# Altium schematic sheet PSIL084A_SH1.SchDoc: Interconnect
size 431 x 279 mm; Date: Not shown in title block; ApprovedBy: Not shown in title block; CheckedBy: Not shown in title block; Author: Not shown in title block; CompanyName: Not shown in title block; DrawnBy: D Strasser; Engineer: Not shown in title block; Organization: Not shown in title block; Address1: Not shown in title block; Address2: Not shown in title block; Address3: Not shown in title block; Address4: Not shown in title block; DocumentNumber: 1; Revision: Use project parameter SCH_Rev; SheetNumber: 1; SheetTotal: 3; PageSetup: Record=PageOptions¦CenterHorizontal=True¦CenterVertical=True¦PrintScale=1.00¦XCorrection=1.00¦YCorrection=1.00¦PrintKind=0¦BorderSize=5000000¦LeftOffset=0¦BottomOffset=0¦Orientation=2¦PaperLength=1000¦PaperWidth=1000¦Scale=100¦PaperSource=15¦PrintQuality=600¦MediaType=1¦DitherType=10¦PaperKind=Letter¦PrintScaleMode=1
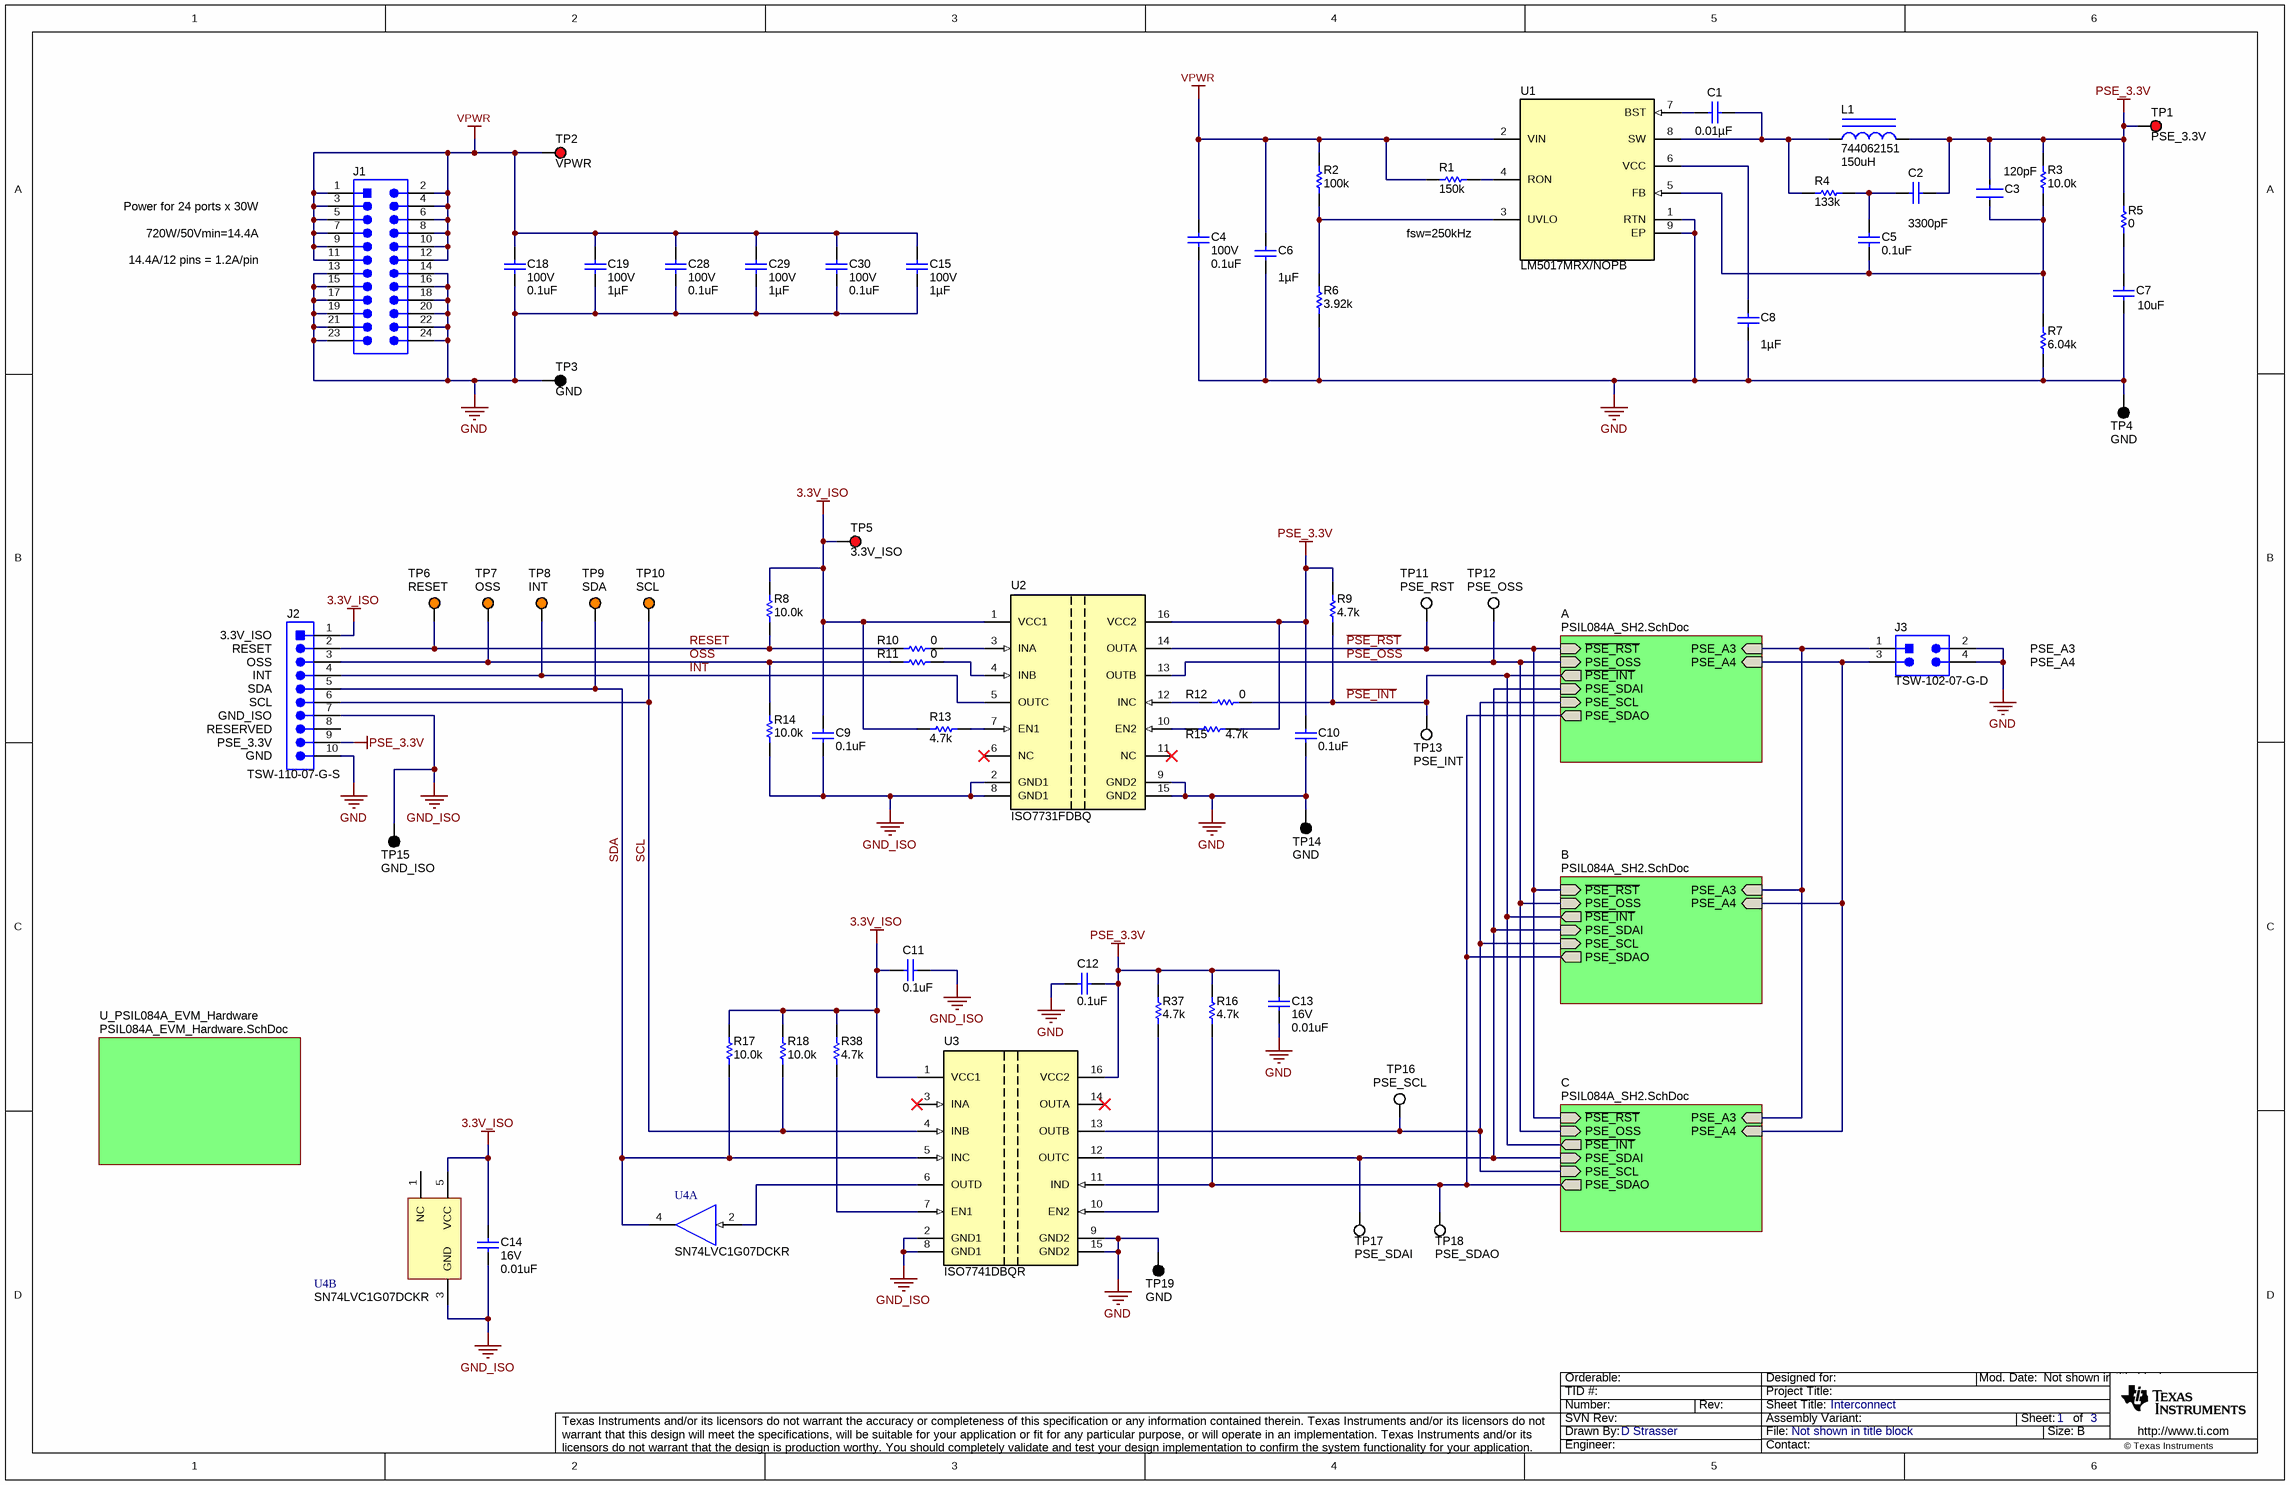
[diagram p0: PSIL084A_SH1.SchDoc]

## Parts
C1  ValueDisplayed: 0.01µF  [0603]  (hidden comment: 885012206089)
C2  ValueDisplayed: 3300pF  [0603]  (hidden comment: GRM1885C1H332JA01D)
C3  Cap_F: 120pF  [FP-GCM1555C1H121FA16D_0402-MFG]  (hidden comment: GCM1555C1H121FA16D)
C4  VDC_V: 100V  ValueDisplayed: 0.1uF  [0805_HV]  (hidden comment: C2012X7R2A104K125AA)
C5  ValueDisplayed: 0.1uF  [0603]  (hidden comment: 885012206095)
C6  ValueDisplayed: 1µF  [1206]  (hidden comment: GCJ31CR72A105KA01K)
C7  ValueDisplayed: 10uF  [0805_HV]  (hidden comment: 885012207026)
C8  ValueDisplayed: 1µF  [0603]  (hidden comment: CL10B105MO8NNWC)
C9  ValueDisplayed: 0.1uF  [0603]  (hidden comment: 885012206095)
C10  ValueDisplayed: 0.1uF  [0603]  (hidden comment: 885012206095)
C11  ValueDisplayed: 0.1uF  [0603]  (hidden comment: 885012206095)
C12  ValueDisplayed: 0.1uF  [0603]  (hidden comment: 885012206095)
C13  VDC_V: 16V  ValueDisplayed: 0.01uF  [0402]  (hidden comment: 885012205031)
C14  VDC_V: 16V  ValueDisplayed: 0.01uF  [0402]  (hidden comment: 885012205031)
C15  VDC_V: 100V  ValueDisplayed: 1µF  [1206]  (hidden comment: GCJ31CR72A105KA01K)
C18  VDC_V: 100V  ValueDisplayed: 0.1uF  [0805L]  (hidden comment: C2012X7R2A104K125AA)
C19  VDC_V: 100V  ValueDisplayed: 1µF  [1206]  (hidden comment: GCJ31CR72A105KA01K)
C28  VDC_V: 100V  ValueDisplayed: 0.1uF  [0805L]  (hidden comment: C2012X7R2A104K125AA)
C29  VDC_V: 100V  ValueDisplayed: 1µF  [1206]  (hidden comment: GCJ31CR72A105KA01K)
C30  VDC_V: 100V  ValueDisplayed: 0.1uF  [0805L]  (hidden comment: C2012X7R2A104K125AA)
J1  TSW-112-07-G-D  [TSW-112-07-G-D]  (value not drawn)
J2  TSW-110-07-G-S  [TSW-110-07-G-S]
J3  TSW-102-07-G-D  [TSW-102-07-G-D]
L1  744062151  ValueDisplayed: 150uH  [WE-TPC_6823]
R1  ValueDisplayed: 150k  [0402]  (hidden comment: CRCW0402150KFKED)
R2  ValueDisplayed: 100k  [0402]  (hidden comment: CRCW0402100KFKED)
R3  ValueDisplayed: 10.0k  [0402]  (hidden comment: CRCW040210K0FKED)
R4  ValueDisplayed: 133k  [0402]  (hidden comment: CRCW0402133KFKED)
R5  ValueDisplayed: 0  [0603]  (hidden comment: RC0603JR-070RL)
R6  ValueDisplayed: 3.92k  [0402]  (hidden comment: CRCW04023K92FKED)
R7  ValueDisplayed: 6.04k  [0402]  (hidden comment: CRCW04026K04FKED)
R8  ValueDisplayed: 10.0k  [0402]  (hidden comment: CRCW040210K0FKED)
R9  ValueDisplayed: 4.7k  [0402]  (hidden comment: CRCW04024K70JNED)
R10  ValueDisplayed: 0  [0402]  (hidden comment: ERJ-2GE0R00X)
R11  ValueDisplayed: 0  [0402]  (hidden comment: ERJ-2GE0R00X)
R12  ValueDisplayed: 0  [0402]  (hidden comment: ERJ-2GE0R00X)
R13  ValueDisplayed: 4.7k  [0402]  (hidden comment: CRCW04024K70JNED)
R14  ValueDisplayed: 10.0k  [0402]  (hidden comment: CRCW040210K0FKED)
R15  ValueDisplayed: 4.7k  [0402]  (hidden comment: CRCW04024K70JNED)
R16  ValueDisplayed: 4.7k  [0402]  (hidden comment: CRCW04024K70JNED)
R17  ValueDisplayed: 10.0k  [0402]  (hidden comment: CRCW040210K0FKED)
R18  ValueDisplayed: 10.0k  [0402]  (hidden comment: CRCW040210K0FKED)
R37  ValueDisplayed: 4.7k  [0402]  (hidden comment: CRCW04024K70JNED)
R38  ValueDisplayed: 4.7k  [0402]  (hidden comment: CRCW04024K70JNED)
TP1  PSE_3.3V  [Keystone5000]
TP2  VPWR  [Keystone5000]
TP3  GND  [Keystone5001]
TP4  GND  [Keystone5001]
TP5  3.3V_ISO  [Keystone5000]
TP6  RESET  [Keystone5003]
TP7  OSS  [Keystone5003]
TP8  INT  [Keystone5003]
TP9  SDA  [Keystone5003]
TP10  SCL  [Keystone5003]
TP11  PSE_RST  [Keystone5002]
TP12  PSE_OSS  [Keystone5002]
TP13  PSE_INT  [Keystone5002]
TP14  GND  [Keystone5001]
TP15  GND_ISO  [Keystone5001]
TP16  PSE_SCL  [Keystone5002]
TP17  PSE_SDAI  [Keystone5002]
TP18  PSE_SDAO  [Keystone5002]
TP19  GND  [Keystone5001]
U1  LM5017MRX/NOPB  [DDA0008B_N]
U2  ISO7731FDBQ  [DBQ0016A_N]
U3  ISO7741DBQR  [DBQ0016A_N]
U4  SN74LVC1G07DCKR  [DCK0005A_N]  (parts A,B of 2)

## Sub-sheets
A = PSIL084A_SH2.SchDoc: ~{PSE_RST} (in), PSE_SCL (in), PSE_SDAI (in), PSE_OSS (in), ~{PSE_INT} (out), PSE_A4 (in), PSE_A3 (in), PSE_SDAO (out)
B = PSIL084A_SH2.SchDoc: ~{PSE_RST} (in), PSE_SCL (in), PSE_SDAI (in), PSE_OSS (in), ~{PSE_INT} (out), PSE_A4 (in), PSE_A3 (in), PSE_SDAO (out)
C = PSIL084A_SH2.SchDoc: ~{PSE_RST} (in), PSE_SCL (in), PSE_SDAI (in), PSE_OSS (in), ~{PSE_INT} (out), PSE_A4 (in), PSE_A3 (in), PSE_SDAO (out)
U_PSIL084A_EVM_Hardware = PSIL084A_EVM_Hardware.SchDoc: no entries

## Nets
3.3V_ISO: C9.1 C11.1 C14.2 J2.1 R8.1 R13.2 R17.1 R18.1 R38.2 TP5.1 U2.1(VCC1) U3.1(VCC1) U4.5(VCC)
GND: C4.1 C6.1 C7.2 C8.2 C10.2 C12.2 C13.1 C15.1 C18.1 C19.1 C28.1 C29.1 C30.1 J1.13 J1.14 J1.15 J1.16 J1.17 J1.18 J1.19 J1.20 J1.21 J1.22 J1.23 J1.24 J2.10 J3.2 J3.4 R6.2 R7.2 TP3.1 TP4.1 TP14.1 TP19.1 U1.1(RTN) U1.9(EP) U2.9(GND2) U2.15(GND2) U3.9(GND2) U3.15(GND2)
GND_ISO: C9.2 C11.2 C14.1 J2.7 R14.2 TP15.1 U2.2(GND1) U2.8(GND1) U3.2(GND1) U3.8(GND1) U4.3(GND)
PSE_3.3V: C2.1 C3.1 C10.1 C12.1 C13.2 J2.9 L1.2 R3.1 R5.1 R9.2 R15.1 R16.2 R37.2 TP1.1 U2.16(VCC2) U3.16(VCC2)
VPWR: C4.2 C6.2 C15.2 C18.2 C19.2 C28.2 C29.2 C30.2 J1.1 J1.2 J1.3 J1.4 J1.5 J1.6 J1.7 J1.8 J1.9 J1.10 J1.11 J1.12 R1.1 R2.1 TP2.1 U1.2(VIN)
~{PSE_INT}: R9.1 R12.2 TP13.1 ; sheet A/~{PSE_INT}, sheet B/~{PSE_INT}, sheet C/~{PSE_INT}
~{PSE_RST}: TP11.1 U2.14(OUTA) ; sheet A/~{PSE_RST}, sheet B/~{PSE_RST}, sheet C/~{PSE_RST}
INT: J2.4 TP8.1 U2.5(OUTC)
OSS: J2.3 R11.1 R14.1 TP7.1
PSE_OSS: TP12.1 U2.13(OUTB) ; sheet A/PSE_OSS, sheet B/PSE_OSS, sheet C/PSE_OSS
RESET: J2.2 R8.2 R10.1 TP6.1
SCL: J2.6 R18.2 TP10.1 U3.4(INB)
SDA: J2.5 R17.2 TP9.1 U3.5(INC) U4.4(Y)
NetC1_1: C1.1 L1.1 R4.1 U1.8(SW)
NetC1_2: C1.2 U1.7(BST)
NetC2_2: C2.2 C5.1 R4.2
NetC3_2: C3.2 C5.2 R3.2 R7.1 U1.5(FB)
NetC7_1: C7.1 R5.2
NetC8_1: C8.1 U1.6(VCC)
NetJ3_1: J3.1 ; sheet A/PSE_A3, sheet B/PSE_A3, sheet C/PSE_A3
NetJ3_3: J3.3 ; sheet A/PSE_A4, sheet B/PSE_A4, sheet C/PSE_A4
NetR1_2: R1.2 U1.4(RON)
NetR2_2: R2.2 R6.1 U1.3(UVLO)
NetR10_2: R10.2 U2.3(INA)
NetR11_2: R11.2 U2.4(INB)
NetR12_1: R12.1 U2.12(INC)
NetR13_1: R13.1 U2.7(EN1)
NetR15_2: R15.2 U2.10(EN2)
NetR16_1: R16.1 TP18.1 U3.11(IND) ; sheet A/PSE_SDAO, sheet B/PSE_SDAO, sheet C/PSE_SDAO
NetR37_1: R37.1 U3.10(EN2)
NetR38_1: R38.1 U3.7(EN1)
NetTP16_1: TP16.1 U3.13(OUTB) ; sheet A/PSE_SCL, sheet B/PSE_SCL, sheet C/PSE_SCL
NetTP17_1: TP17.1 U3.12(OUTC) ; sheet A/PSE_SDAI, sheet B/PSE_SDAI, sheet C/PSE_SDAI
NetU3_6: U3.6(OUTD) U4.2(A)

Not connected (* = marked no-connect by the designer): J2 8; U2 6(NC)* 11(NC)*; U3 3(INA)* 14(OUTA)*; U4 1(NC)

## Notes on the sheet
- Power for 24 ports x 30W
- 720W/50Vmin=14.4A
- fsw=250kHz
- 14.4A/12 pins = 1.2A/pin
- (near J2) 3.3V_ISO
- (near J2) RESET
- (near J2) OSS
- (near J2) INT
- (near J2) SDA
- (near J2) SCL
- PSE_A3
- PSE_A4
- (near J2) GND_ISO
- (near J2) GND
- (near J2) PSE_3.3V
- (near J2) RESERVED

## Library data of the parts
C1 = CMP-0750039-1: CAP, CERM, 0.01 µF, 50 V,+/- 10%, X7R, 0603; Manufacturer: Wurth Elektronik; Polarized: N; AEC Category: Q200; TaMax_C: 125°C; SizeAreaWB_mm2: 4.68; Value: 0.01uF; CompType: Capacitor; SizeArea_mm2: 1.28; SizeY_mm: 0.8; SizeZ_mm: 1; SizeX_mm: 1.6; VDC_V: 50V; U/M: EA; Cap_F: 10nF; TaMin_C: -55°C
C2 = CMP-0007210-4: CAP, CERM, 3300 pF, 50 V, +/- 5%, C0G/NP0, 0603; Manufacturer: MuRata; TaMin_C: -55°C; Polarized: N; SizeAreaWB_mm2: 4.68; Value1: Unknown; U/M: EA; Value: 3300pF; TaMax_C: 125°C; SizeZ_mm: 1; SizeX_mm: 1.6; SizeY_mm: 0.8; Value2: 50V; SizeArea_mm2: 1.28; CompType: Capacitor; Cap_F: 3.3nF; AEC Category: Q200
C3 = CMP-0086511-1: 120pF ±1% 50V Ceramic Capacitor C0G, NP0 0402 (1005 Metric); Manufacturer: Murata; AEC Qualified: Yes; TempCo: 30ppm/°C; SizeZ_mm: 0.55mm; Symbol Name: SYM-GCM1555C1H121FA16D; AEC Grade: Grade 1
C4 C18 C28 C30 = CMP-0007886-2: CAP, CERM, 0.1 uF, 100 V, +/- 10%, X7R, 0805; Manufacturer: TDK; TaMin_C: -55°C; ESR_ohm: 0.020726; Polarized: N; SizeAreaWB_mm2: 6.75; Value1: 0.020726 ohm; U/M: EA; Value: 0.1uF; TaMax_C: 125°C; SizeZ_mm: 1.45; SizeX_mm: 2; SizeY_mm: 1.25; Cap_Case: 0805; SizeArea_mm2: 2.5; Cap_F: 100nF; IRMS_A: 1.456A; AEC Category: Q200
C5 C9-C12 = CMP-0006837-4: CAP, CERM, 0.1 uF, 50 V, +/- 10%, X7R, 0603; Manufacturer: Wurth Elektronik; TaMin_C: -55°C; Polarized: N; SizeAreaWB_mm2: 4.68; Value1: Unknown; U/M: EA; Value: 0.1uF; TaMax_C: 125°C; SizeZ_mm: 1; SizeX_mm: 1.6; SizeY_mm: 0.8; Value2: 50V; SizeArea_mm2: 1.28; CompType: Capacitor; Cap_F: 100nF; AEC Category: Q200
C6 = CMP-0750040-1: CAP, CERM, 1 µF, 100 V,+/- 10%, X7R, AEC-Q200 Grade 1, 1206; Manufacturer: MuRata; Value: 1uF; VDC_V: 100V; U/M: EA; SizeX_mm: 3.2; Polarized: N; TaMin_C: -55°C; SizeZ_mm: 1.35; SizeY_mm: 1.6; AEC Category: Q200; SizeArea_mm2: 5.12; TaMax_C: 125°C; AEC Grade: 1; CompType: Capacitor; AEC Qualified: Y; SizeAreaWB_mm2: 10.92
C7 = CMP-0007691-2: CAP, CERM, 10 uF, 10 V, +/- 10%, X7R, 0805; Manufacturer: Wurth Elektronik; TaMin_C: -55°C; Polarized: N; SizeAreaWB_mm2: 6.75; Value1: Unknown; U/M: EA; Value: 10uF; TaMax_C: 125°C; SizeZ_mm: 1.45; SizeX_mm: 2; SizeY_mm: 1.25; Cap_Case: 0805; Value2: 10V; SizeArea_mm2: 2.5; CompType: Capacitor; Cap_F: 10µF; AEC Category: Q200
C8 = CMP-0082012-1: CAP, CERM, 1 µF, 16 V,+/- 20%, X7R, 0603; Manufacturer: Samsung; SizeAreaWB_mm2: 4.68; SizeArea_mm2: 1.28; AEC Qualified: N; AEC Category: Q200; Value: 1uF; TaMax_C: 125°C; SizeZ_mm: 1; TaMin_C: -55°C; VDC_V: 16V; SizeY_mm: 0.8; U/M: EA; CompType: Capacitor; SizeX_mm: 1.6
C13 C14 = CMP-0006227-2: CAP, CERM, 0.01 uF, 16 V, +/- 10%, X7R, 0402; Manufacturer: Wurth Elektronik; TaMin_C: -55°C; Polarized: N; SizeAreaWB_mm2: 3; Value1: Unknown; U/M: EA; Value: 0.01uF; TaMax_C: 125°C; SizeZ_mm: 0.6; SizeX_mm: 1; SizeY_mm: 0.5; Cap_F: 10nF; AEC Category: Q200
C15 C19 C29 = CMP-0750040-1: CAP, CERM, 1 µF, 100 V,+/- 10%, X7R, AEC-Q200 Grade 1, 1206; Manufacturer: MuRata; Value: 1uF; U/M: EA; SizeX_mm: 3.2; Polarized: N; TaMin_C: -55°C; SizeZ_mm: 1.35; SizeY_mm: 1.6; AEC Category: Q200; SizeArea_mm2: 5.12; TaMax_C: 125°C; AEC Grade: 1; CompType: Capacitor; AEC Qualified: Y; SizeAreaWB_mm2: 10.92
J1 = CMP-0075423-1: Header, 100mil, 12x2, Gold, TH; Manufacturer: Samtec; Pitch_mm: 2.54; Cert_VDE: N; Gender: Male; Cert_CSA: Y; Current_A: 6.3A; Voltage_V: 550V; CT: False; Row_Count: 2; CNHeader: True
J2 = CMP-0075422-1: Header, 100mil, 10x1, Gold, TH; Manufacturer: Samtec; Pitch_mm: 2.54; Cert_VDE: N; Gender: Male; Cert_CSA: Y; Voltage_V: 550V; Green_REACh: Passed; Current_A: 6.3A; CT: False; Green_Lifecycle: Active; Row_Count: 1; CNHeader: True
J3 = CMP-0075404-1: Header, 100mil, 2x2, Gold, TH; Manufacturer: Samtec; Pitch_mm: 2.54; Cert_VDE: N; Gender: Male; Cert_CSA: Y; Voltage_V: 550V; Green_REACh: Passed; Current_A: 6.3A; CT: False; Green_Lifecycle: Active; Row_Count: 2; CNHeader: True
L1 = CMP-0064704-3: Inductor, Shielded Drum Core, Ferrite, 150 uH, 0.36 A, 0.605 ohm, SMD; Manufacturer: Wurth Elektronik; Isat: 0.36A @ 35% inductance drop; Irms: 0.43A @ 30C rise; Green_Lifecycle: Active; SizeAreaWB_mm2: 77.44; DCR_ohm: 6.05d; Green_REACh: Passed; Value: 150uH; Imax_A: 3.6dA; SizeZ_mm: 2.5; SizeX_mm: 6.8; Value2: 0.36A; SizeArea_mm2: 46.24; Ind_H: 150µH; AEC Qualified: N; AEC Category: Q200
R1 = CMP-0026021-3: RES, 150 k, 1%, 0.063 W, AEC-Q200 Grade 0, 0402; Manufacturer: Vishay-Dale; Power_W: 63mW; TempCo: 100 ppm/C; Value: 150k; EIA_Code: E96; SizeX_mm: 1; SizeY_mm: 0.5; SizeZ_mm: 0.6; Value2: 0.063W; AEC Qualified: Y; VDC_V: 50V; AEC Category: Q200; AEC Grade: 0
R2 = CMP-0025950-3: RES, 100 k, 1%, 0.063 W, AEC-Q200 Grade 0, 0402; Manufacturer: Vishay-Dale; Power_W: 63mW; TempCo: 100 ppm/C; Value: 100k; EIA_Code: E96; SizeX_mm: 1; SizeY_mm: 0.5; SizeZ_mm: 0.6; Value2: 0.063W; AEC Qualified: Y; VDC_V: 50V; AEC Category: Q200; AEC Grade: 0
R3 R8 R14 R17 R18 = CMP-0025958-3: RES, 10.0 k, 1%, 0.063 W, AEC-Q200 Grade 0, 0402; Manufacturer: Vishay-Dale; Power_W: 63mW; TempCo: 100 ppm/C; Value_Code: 10k0; Value: 10.0k; EIA_Code: E96; Res_ohm: 10k; SizeX_mm: 1; SizeY_mm: 0.5; SizeZ_mm: 0.6; Value2: 0.063W; AEC Qualified: Y; VDC_V: 50V; AEC Category: Q200; AEC Grade: 0
R4 = CMP-0025999-3: RES, 133 k, 1%, 0.063 W, AEC-Q200 Grade 0, 0402; Manufacturer: Vishay-Dale; Power_W: 63mW; TempCo: 100 ppm/C; Value: 133k; EIA_Code: E96; SizeX_mm: 1; SizeY_mm: 0.5; SizeZ_mm: 0.6; Value2: 0.063W; AEC Qualified: Y; VDC_V: 50V; AEC Category: Q200; AEC Grade: 0
R5 = CMP-0025885-5: RES, 0, 5%, 0.1 W, 0603; Manufacturer: Yageo; Power_W: 100mW; TempCo: 200 ppm/C; Value_Code: 0000; Value: 0; EIA_Code: E24; SizeX_mm: 1.6; SizeZ_mm: 1; Value2: 0.1W; SizeArea_mm2: 1.28; AEC Qualified: N; VDC_V: 75V; AEC Category: Q200; SizeY_mm: 0.8; SizeAreaWB_mm2: 4.68
R6 = CMP-0026340-2: RES, 3.92 k, 1%, 0.063 W, AEC-Q200 Grade 0, 0402; Manufacturer: Vishay-Dale; Power_W: 63mW; TempCo: 100 ppm/C; Value_Code: 3k92; Value: 3.92k; EIA_Code: E96; SizeX_mm: 1; SizeY_mm: 0.5; SizeZ_mm: 0.6; Value2: 0.063W; AEC Qualified: Y; VDC_V: 50V; AEC Category: Q200; AEC Grade: 0
R7 = CMP-0026512-2: RES, 6.04 k, 1%, 0.063 W, AEC-Q200 Grade 0, 0402; Manufacturer: Vishay-Dale; Power_W: 63mW; TempCo: 100 ppm/C; Value_Code: 6k04; Value: 6.04k; EIA_Code: E96; SizeX_mm: 1; SizeY_mm: 0.5; SizeZ_mm: 0.6; Value2: 0.063W; AEC Qualified: Y; VDC_V: 50V; AEC Category: Q200; AEC Grade: 0
R9 R13 R15 R16 R37 R38 = CMP-0026938-5: RES, 4.7 k, 5%, 0.063 W, AEC-Q200 Grade 0, 0402; Manufacturer: Vishay-Dale; Power_W: 63mW; TempCo: 200 ppm/C; Value_Code: 4k70; Value: 4.7k; EIA_Code: E24; SizeX_mm: 1; SizeY_mm: 0.5; SizeZ_mm: 0.6; Value2: 0.063W; AEC Qualified: Y; VDC_V: 50V; AEC Grade: 0; AEC Category: Q200
R10-R12 = CMP-0026992-3: RES, 0, 5%, 0.1 W, AEC-Q200 Grade 0, 0402; Manufacturer: Panasonic; Power_W: 100mW; TempCo: 600 ppm/C; Value_Code: 0000; Value: 0; EIA_Code: E24; SizeX_mm: 1; SizeY_mm: 0.5; SizeZ_mm: 0.6; Value2: 0.1W; AEC Qualified: Y; VDC_V: 50V; AEC Category: Q200; SizeAreaWB_mm2: 3
TP1 TP2 TP5 = CMP-0055137-1: Test Point, Miniature, Red, TH; Manufacturer: Keystone; PartNumber: 5000; CNHeader: FALSE; Green_Lifecycle: Active; Green_REACh: Passed; ContactFinish: Silver; CT: TRUE
TP3 TP4 TP14 TP15 TP19 = CMP-0055138-1: Test Point, Miniature, Black, TH; Manufacturer: Keystone; PartNumber: 5001; CNHeader: FALSE; Green_Lifecycle: Active; Green_REACh: Passed; ContactFinish: Silver; CT: TRUE
TP6-TP10 = CMP-0055140-1: Test Point, Miniature, Orange, TH; Manufacturer: Keystone; PartNumber: 5003; CNHeader: FALSE; Green_Lifecycle: Active; Green_REACh: Passed; ContactFinish: Silver; CT: TRUE
TP11-TP13 TP16-TP18 = CMP-0055139-1: Test Point, Miniature, White, TH; Manufacturer: Keystone; PartNumber: 5002; CNHeader: FALSE; Green_Lifecycle: Active; Green_REACh: Passed; ContactFinish: Silver; CT: TRUE
U1 = CMP-0066086-2: 7.5-100V Wide Vin, 600mA Constant On-Time Synchronous Buck Regulator, DDA0008B (SOIC-8); Manufacturer: Texas Instruments; Alternate PartNumber: LM5017MR/NOPB; SizeX_mm: 5.0; SizeY_mm: 6.2; CompType: IC; SizeZ_mm: 1.7; SizeArea_mm2: 31.0; SizeAreaWB_mm2: 57.4; U/M: EA
U2 = CMP-0078720-1: High Speed, Robust EMC Triple-Channel Digital Isolators, DBQ0016A (SSOP-16); Alternate PartNumber: ISO7731FDBQR; Manufacturer: Texas Instruments; SizeZ_mm: 1.75; SizeX_mm: 6; SizeY_mm: 10; SizeArea_mm2: 60; CompType: IC; SizeAreaWB_mm2: 96; AEC Qualified: N; AEC Category: Q200
U3 = CMP-0013040-3: High Speed, Robust EMC Quad-Channel Digital Isolators, DBQ0016A (SSOP-16); Manufacturer: Texas Instruments; SizeX_mm: 6; SizeY_mm: 10; CompType: IC; SizeZ_mm: 1.75; SizeArea_mm2: 60; SizeAreaWB_mm2: 96; AEC Category: Q200; AEC Qualified: N
U4 = CMP-0051390-2: Single Buffer/Driver With Open-Drain Output, DCK0005A, LARGE T&R; Manufacturer: Texas Instruments; 3-State Output: No; F @ Nom Voltage(Max)(Mhz): 150; ICC @ Nom Voltage(Max)(mA): 0.01; VCC(Min)(V): 1.65; Logic: True; Sub-Family: Non-Inverting Buffer/Driver; Output Drive (IOL/IOH)(Max)(mA): 32/-32; Input Type: CMOS/TTL; Technology Family: LVC; Bits(#): 1; VCC(Max)(V): 5.5; Output Type: CMOS; tpd @ Nom Voltage(Max)(ns): 8.6,6,4.7,4; Rating: Catalog; Voltage(Nom)(V): 1.8,2.5,3.3,5; AEC Category: Q200; AEC Qualified: N; CompType: IC; SizeAreaWB_mm2: 9.3; SizeArea_mm2: 4.2; SizeX_mm: 2.1; SizeY_mm: 2.0; SizeZ_mm: 1.1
